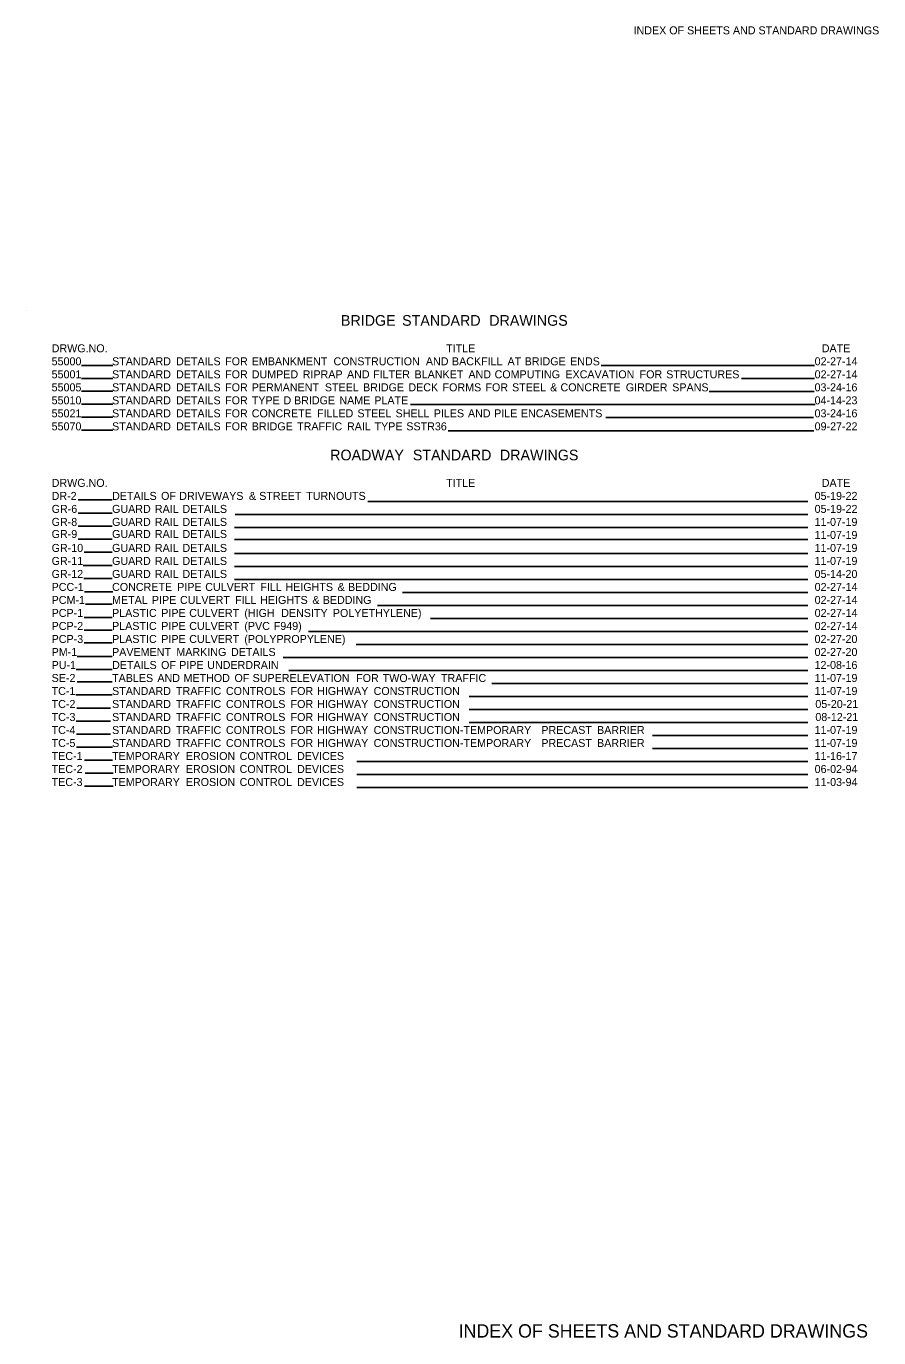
# Model space of a CAD drawing. Extents: x -1392 to 1630, y -1031 to 935.
# Drawn here: x 352 to 1630, y -1031 to 935 of the extents above; entities that cross this region are included whole.
import ezdxf

# ---------------------------------------------------------------- set-up
doc = ezdxf.new("R2010")
doc.units = 0
for name, color, linetype in [('Default', 7, 'Continuous'), ('R_Border', 7, 'Continuous'), ('R_Border Prem', 7, 'Continuous')]:
    doc.layers.add(name, color=color, linetype=linetype)

msp = doc.modelspace()

# ---------------------------------------------------------------- linework, layer by layer
at = {"layer": 'Default'}
for p, q in [((352.3, 509.5), (352.3, 509.5)), ((435.3, 426.7), (481.9, 426.7)), ((1214, 426.9), (1533.9, 426.9)), ((435.3, 407.3), (481.9, 407.3)), ((1424.5, 407.1), (1533.9, 407.1)), ((435.3, 388), (481.9, 388)), ((1375.8, 387.7), (1533.2, 387.7)), ((435.3, 368.7), (481.9, 368.7)), ((928.2, 368.4), (1534.9, 368.4)), ((435.3, 349.3), (481.9, 349.3)), ((1220.9, 348.6), (1532.5, 348.6)), ((435.3, 330), (481.9, 330)), ((984.8, 329), (1532.7, 329)), ((430.4, 225.2), (481, 225.2)), ((864.5, 222.8), (1523.9, 222.8)), ((430.4, 205.5), (481.1, 205.5)), ((665.3, 203.3), (1523.9, 203.3)), ((430.4, 185.9), (481.1, 185.9)), ((664.5, 183.8), (1523.9, 183.8)), ((430.4, 166.2), (481.1, 166.2)), ((664.5, 165.7), (1523.9, 165.7)), ((439, 146.6), (481.1, 146.6)), ((664.5, 144.8), (1523.9, 144.8)), ((437.7, 126.9), (481.1, 126.9)), ((664.5, 125.3), (1523.9, 125.3)), ((438.8, 107.3), (481.1, 107.3)), ((664.5, 105.8), (1523.9, 105.8)), ((439.9, 87.6), (482.2, 87.6)), ((916.4, 86.3), (1523.9, 86.3)), ((441, 68.8), (480.9, 68.8)), ((878.9, 66.8), (1523.9, 66.8)), ((439.4, 49.1), (481.2, 49.1)), ((958.5, 47.3), (1523.9, 47.3)), ((439.4, 29.9), (481.2, 29.9)), ((775.4, 27.8), (1523.9, 27.8)), ((439.4, 10.8), (481.2, 10.8)), ((846.8, 8.3), (1523.9, 8.3)), ((428.5, -9.7), (481.2, -9.7)), ((737.7, -11.2), (1523.9, -11.2)), ((427, -29), (481.2, -29)), ((746.1, -30.7), (1523.9, -30.7)), ((428.9, -47.5), (481.2, -47.5)), ((1050.2, -50.2), (1523.9, -50.2)), ((426.6, -67), (481.2, -67)), ((1016.5, -69.7), (1523.9, -69.7)), ((428.1, -87.2), (478.8, -87.2)), ((1016.5, -89.2), (1523.9, -89.2)), ((427, -106.6), (478.8, -106.6)), ((1016.5, -108.7), (1523.9, -108.7)), ((427.7, -126.1), (478.8, -126.1)), ((1290.9, -128.2), (1523.9, -128.2)), ((427.7, -145.4), (481.6, -145.4)), ((1290.9, -147.7), (1523.9, -147.7)), ((439.8, -165.1), (481.6, -165.1)), ((847.9, -167.2), (1523.9, -167.2)), ((440.7, -184.5), (482.8, -184.5)), ((847.9, -186.7), (1523.9, -186.7)), ((439.6, -203.8), (482.8, -203.8)), ((847.9, -206.2), (1523.9, -206.2))]:
    msp.add_line(p, q, dxfattribs=at)

# ---------------------------------------------------------------- texts
for s, height, p in [('BRIDGE', 16, (824, 486.3)), (' STANDARD', 16, (909.8, 486.3)), (' DRAWINGS', 16, (1040.4, 486.3)), ('DRWG.NO.', 12, (390.5, 446.5)), ('TITLE', 12, (981.7, 446.5)), ('DATE', 12, (1544.8, 446.5)), ('55000', 12, (390.4, 427)), ('STANDARD', 12, (481, 427)), (' DETAILS', 12, (572.4, 427)), (' FOR', 12, (646, 427)), (' EMBANKMENT', 12, (685.9, 427)), (' CONSTRUCTION', 12, (808.5, 427)), (' AND', 12, (946.9, 427)), (' BACKFILL', 12, (986, 427)), (' AT', 12, (1069.3, 427)), (' BRIDGE', 12, (1095, 427)), (' ENDS', 12, (1163.1, 427)), ('02-27-14', 12, (1534.1, 427)), ('55001', 12, (390.4, 407.5)), ('STANDARD', 12, (481, 407.5)), (' DETAILS', 12, (572.4, 407.5)), (' FOR', 12, (646, 407.5)), (' DUMPED', 12, (685.9, 407.5)), (' RIPRAP', 12, (762.3, 407.5)), (' AND', 12, (828.7, 407.5)), (' FILTER', 12, (867.8, 407.5)), (' BLANKET', 12, (930, 407.5)), (' AND', 12, (1010.7, 407.5)), (' COMPUTING', 12, (1049.9, 407.5)), (' EXCAVATION', 12, (1156, 407.5)), (' FOR', 12, (1267.3, 407.5)), (' STRUCTURES', 12, (1307.2, 407.5)), ('02-27-14', 12, (1534.1, 407.5)), ('55005', 12, (390.4, 388)), ('STANDARD', 12, (481, 388)), (' DETAILS', 12, (572.4, 388)), (' FOR', 12, (646, 388)), (' PERMANENT', 12, (685.9, 388)), (' STEEL', 12, (795.5, 388)), (' BRIDGE', 12, (852.7, 388)), (' DECK', 12, (920.7, 388)), (' FORMS', 12, (971.9, 388)), (' FOR', 12, (1036.2, 388)), (' STEEL', 12, (1076.1, 388)), (' &', 12, (1133.2, 388)), (' CONCRETE', 12, (1148.7, 388)), (' GIRDER', 12, (1246.6, 388)), (' SPANS', 12, (1316.2, 388)), ('03-24-16', 12, (1534, 388)), ('55010', 12, (390.4, 368.5)), ('STANDARD', 12, (481, 368.5)), (' DETAILS', 12, (572.4, 368.5)), (' FOR', 12, (646, 368.5)), (' TYPE', 12, (685.9, 368.5)), (' D', 12, (733.4, 368.5)), (' BRIDGE', 12, (749.3, 368.5)), (' NAME', 12, (817.3, 368.5)), (' PLATE', 12, (869.6, 368.5)), ('04-14-23', 12, (1534, 368.5)), ('55021', 12, (390.4, 349)), ('STANDARD', 12, (481, 349)), (' DETAILS', 12, (572.4, 349)), (' FOR', 12, (646, 349)), (' CONCRETE', 12, (685.9, 349)), (' FILLED', 12, (783.7, 349)), (' STEEL', 12, (844.3, 349)), (' SHELL', 12, (901.5, 349)), (' PILES', 12, (958.7, 349)), (' AND', 12, (1010, 349)), (' PILE', 12, (1049.2, 349)), (' ENCASEMENTS', 12, (1089.3, 349)), ('03-24-16', 12, (1534, 349)), ('55070', 12, (390.4, 329.5)), ('STANDARD', 12, (481, 329.5)), (' DETAILS', 12, (572.4, 329.5)), (' FOR', 12, (646, 329.5)), (' BRIDGE', 12, (685.9, 329.5)), (' TRAFFIC', 12, (753.9, 329.5)), (' RAIL', 12, (828.7, 329.5)), (' TYPE', 12, (870, 329.5)), (' SSTR36', 12, (917.6, 329.5)), ('09-27-22', 12, (1534.1, 329.5)), ('ROADWAY', 16, (807.9, 284.5)), (' STANDARD', 16, (925.9, 284.5)), (' DRAWINGS', 16, (1056.4, 284.5)), ('DRWG.NO.', 12, (390.5, 244.7)), ('TITLE', 12, (981.7, 244.7)), ('DATE', 12, (1544.8, 244.7)), ('DR-2', 12, (390.4, 225.2)), ('DETAILS', 12, (481, 225.2)), (' OF', 12, (550, 225.2)), (' DRIVEWAYS', 12, (577.2, 225.2)), (' &', 12, (681.6, 225.2)), (' STREET', 12, (697.1, 225.2)), (' TURNOUTS', 12, (767.6, 225.2)), ('05-19-22', 12, (1534.1, 225.2)), ('GR-6', 12, (390.4, 205.7)), ('GUARD', 12, (481, 205.7)), (' RAIL', 12, (540.7, 205.7)), (' DETAILS', 12, (582, 205.7)), ('05-19-22', 12, (1534.1, 205.7)), ('GR-8', 12, (390.4, 186.2)), ('GUARD', 12, (481, 186.2)), (' RAIL', 12, (540.7, 186.2)), (' DETAILS', 12, (582, 186.2)), ('11-07-19', 12, (1534, 186.2)), ('GR-9', 12, (390.4, 168.1)), ('GUARD', 12, (481, 168.1)), (' RAIL', 12, (540.7, 168.1)), (' DETAILS', 12, (582, 168.1)), ('11-07-19', 12, (1534, 166.7)), ('GR-10', 12, (390.4, 147.2)), ('GUARD', 12, (481, 147.2)), (' RAIL', 12, (540.7, 147.2)), (' DETAILS', 12, (582, 147.2)), ('11-07-19', 12, (1534, 147.2)), ('GR-11', 12, (390.4, 127.7)), ('GUARD', 12, (481, 127.7)), (' RAIL', 12, (540.7, 127.7)), (' DETAILS', 12, (582, 127.7)), ('11-07-19', 12, (1534, 127.7)), ('GR-12', 12, (390.4, 108.2)), ('GUARD', 12, (481, 108.2)), (' RAIL', 12, (540.7, 108.2)), (' DETAILS', 12, (582, 108.2)), ('05-14-20', 12, (1534, 108.2)), ('PCC-1', 12, (390.4, 88.7)), ('CONCRETE', 12, (481, 88.7)), (' PIPE', 12, (574.2, 88.7)), (' CULVERT', 12, (616.2, 88.7)), (' FILL', 12, (698.8, 88.7)), (' HEIGHTS', 12, (736.4, 88.7)), (' &', 12, (814.7, 88.7)), (' BEDDING', 12, (830.2, 88.7)), ('02-27-14', 12, (1534.1, 88.7)), ('PCM-1', 12, (390.4, 69.2)), ('METAL', 12, (481, 69.2)), (' PIPE', 12, (536.3, 69.2)), (' CULVERT', 12, (578.3, 69.2)), (' FILL', 12, (660.9, 69.2)), (' HEIGHTS', 12, (698.5, 69.2)), (' &', 12, (776.8, 69.2)), (' BEDDING', 12, (792.3, 69.2)), ('02-27-14', 12, (1534.1, 69.2)), ('PCP-1', 12, (390.4, 49.7)), ('PLASTIC', 12, (481, 49.7)), (' PIPE', 12, (550.3, 49.7)), (' CULVERT', 12, (592.2, 49.7)), (' (HIGH', 12, (674.8, 49.7)), ('  DENSITY', 12, (725.6, 49.7)), (' POLYETHYLENE)', 12, (807.5, 49.7)), ('02-27-14', 12, (1534.1, 49.7)), ('PCP-2', 12, (390.4, 30.2)), ('PLASTIC', 12, (481, 30.2)), (' PIPE', 12, (550.3, 30.2)), (' CULVERT', 12, (592.2, 30.2)), (' (PVC', 12, (674.8, 30.2)), (' F949)', 12, (718.9, 30.2)), ('02-27-14', 12, (1534.1, 30.2)), ('PCP-3', 12, (390.4, 10.7)), ('PLASTIC', 12, (481, 10.7)), (' PIPE', 12, (550.3, 10.7)), (' CULVERT', 12, (592.2, 10.7)), (' (POLYPROPYLENE)', 12, (674.8, 10.7)), ('02-27-20', 12, (1534, 10.7)), ('PM-1', 12, (390.4, -8.8)), ('PAVEMENT', 12, (481, -8.8)), (' MARKING', 12, (572.9, -8.8)), (' DETAILS', 12, (654.8, -8.8)), ('02-27-20', 12, (1534, -8.8)), ('PU-1', 12, (390.4, -28.3)), ('DETAILS', 12, (481, -28.3)), (' OF', 12, (550, -28.3)), (' PIPE', 12, (577.2, -28.3)), (' UNDERDRAIN', 12, (619.2, -28.3)), ('12-08-16', 12, (1534, -28.3)), ('SE-2', 12, (390.4, -47.8)), ('TABLES', 12, (481, -47.8)), (' AND', 12, (544.5, -47.8)), (' METHOD', 12, (583.6, -47.8)), (' OF', 12, (660, -47.8)), (' SUPERELEVATION', 12, (687.2, -47.8)), (' FOR', 12, (842.4, -47.8)), (' TWO-WAY', 12, (882.2, -47.8)), (' TRAFFIC', 12, (969.6, -47.8)), ('11-07-19', 12, (1534, -47.8)), ('TC-1', 12, (390.4, -67.3)), ('STANDARD', 12, (481, -67.3)), (' TRAFFIC', 12, (572.4, -67.3)), (' CONTROLS', 12, (647.2, -67.3)), (' FOR', 12, (744.1, -67.3)), (' HIGHWAY', 12, (783.9, -67.3)), (' CONSTRUCTION', 12, (868.6, -67.3)), ('11-07-19', 12, (1534, -67.3)), ('TC-2', 12, (390.4, -86.8)), ('STANDARD', 12, (481, -86.8)), (' TRAFFIC', 12, (572.4, -86.8)), (' CONTROLS', 12, (647.2, -86.8)), (' FOR', 12, (744.1, -86.8)), (' HIGHWAY', 12, (783.9, -86.8)), (' CONSTRUCTION', 12, (868.6, -86.8)), ('05-20-21', 12, (1535.2, -86.8)), ('TC-3', 12, (390.4, -106.3)), ('STANDARD', 12, (481, -106.3)), (' TRAFFIC', 12, (572.4, -106.3)), (' CONTROLS', 12, (647.2, -106.3)), (' FOR', 12, (744.1, -106.3)), (' HIGHWAY', 12, (783.9, -106.3)), (' CONSTRUCTION', 12, (868.6, -106.3)), ('08-12-21', 12, (1535.2, -106.3)), ('TC-4', 12, (390.4, -125.8)), ('STANDARD', 12, (481, -125.8)), (' TRAFFIC', 12, (572.4, -125.8)), (' CONTROLS', 12, (647.2, -125.8)), (' FOR', 12, (744.1, -125.8)), (' HIGHWAY', 12, (783.9, -125.8)), (' CONSTRUCTION-TEMPORARY', 12, (868.6, -125.8)), (' PRECAST', 12, (1120, -125.8)), (' BARRIER', 12, (1203.5, -125.8)), ('11-07-19', 12, (1534, -125.8)), ('TC-5', 12, (390.4, -145.3)), ('STANDARD', 12, (481, -145.3)), (' TRAFFIC', 12, (572.4, -145.3)), (' CONTROLS', 12, (647.2, -145.3)), (' FOR', 12, (744.1, -145.3)), (' HIGHWAY', 12, (783.9, -145.3)), (' CONSTRUCTION-TEMPORARY', 12, (868.6, -145.3)), (' PRECAST', 12, (1120, -145.3)), (' BARRIER', 12, (1203.5, -145.3)), ('11-07-19', 12, (1534, -145.3)), ('TEC-1', 12, (390.4, -164.8)), ('TEMPORARY', 12, (481, -164.8)), (' EROSION', 12, (587.1, -164.8)), (' CONTROL', 12, (667.7, -164.8)), (' DEVICES', 12, (753.8, -164.8)), ('11-16-17', 12, (1534, -164.8)), ('TEC-2', 12, (390.4, -184.3)), ('TEMPORARY', 12, (481, -184.3)), (' EROSION', 12, (587.1, -184.3)), (' CONTROL', 12, (667.7, -184.3)), (' DEVICES', 12, (753.8, -184.3)), ('06-02-94', 12, (1534.1, -184.3)), ('TEC-3', 12, (390.4, -203.8)), ('TEMPORARY', 12, (481, -203.8)), (' EROSION', 12, (587.1, -203.8)), (' CONTROL', 12, (667.7, -203.8)), (' DEVICES', 12, (753.8, -203.8)), ('11-03-94', 12, (1534.1, -203.8))]:
    msp.add_text(s, height=height, dxfattribs=at).set_placement(p)
at = {"layer": 'R_Border'}
msp.add_text('INDEX OF SHEETS AND STANDARD DRAWINGS', height=20, dxfattribs=at).set_placement((1000.4, -1030.7))
at = {"layer": 'R_Border Prem'}
msp.add_text('INDEX OF SHEETS AND STANDARD DRAWINGS ', height=12, dxfattribs=at).set_placement((1262.7, 923.2))

doc.saveas('drawing.dxf')
